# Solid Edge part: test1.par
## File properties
Author: CADCIM
Template: Normal.par
Last saved by: Cadcim
Revision: 2
Application: Solid Edge
Accuracy: 0.99
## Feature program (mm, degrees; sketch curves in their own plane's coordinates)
sketch for "unnamed Protrusion 1" #1 plane through (0, 0, 0) normal (0, 0, 1) x-axis (1, 0, 0)
  line (-47.52, 0) -> (-47.52, 46.944)
  line (-47.52, 46.944) -> (47.52, 46.944)
  line (47.52, 46.944) -> (47.52, 0)
  line (47.52, 0) -> (-47.52, 0)
sketch for "unnamed Protrusion 1" #2 plane through (0, 0, 0) normal (0, 0, 1) x-axis (1, 0, 0)
  circle centre (-33.4173, 33.1293) radius 7.1111
sketch for "unnamed Protrusion 1" #3 plane through (0, 0, 0) normal (0, 0, 1) x-axis (1, 0, 0)
  circle centre (0, 13.2015) radius 7.2161
sketch for "unnamed Protrusion 1" #4 plane through (0, 0, 0) normal (0, 0, 1) x-axis (1, 0, 0)
  circle centre (36.4831, 33.1293) radius 6.1622
extrude "unnamed Protrusion 1" add finite 6.35 along +normal
sketch for "ExtrudedProtrusion_2" #1 plane through (0, 23.472, 6.35) normal (0, 0, 1) x-axis (0, 1, 0)
sketch for "ExtrudedProtrusion_2" #2 plane through (0, 23.472, 6.35) normal (0, 0, 1) x-axis (0, 1, 0)
sketch for "ExtrudedProtrusion_2" #3 plane through (0, 23.472, 6.35) normal (0, 0, 1) x-axis (0, 1, 0)
  circle centre (-10.2705, 0) radius 7.2161
extrude "ExtrudedProtrusion_2" add finite 28.575 along -normal
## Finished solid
Body 1: solid body, 12 faces, 18 edges, 8 vertices.
  Faces by surface: plane 9, cylinder 3
  Edges by curve: line 12, circle 6
Bounding box of the edges (mm): 95.040 x 46.944 x 28.575, from (-47.52, 0, -22.225) to (47.52, 46.944, 6.35).
Cylindrical faces by radius (mm): R6.1622 x1, R7.1111 x1, R7.2161 x1
Planar faces by outward normal: +x 1, +y 1, +z 1, -x 1, -y 1, -z 4
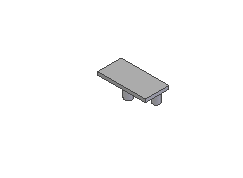
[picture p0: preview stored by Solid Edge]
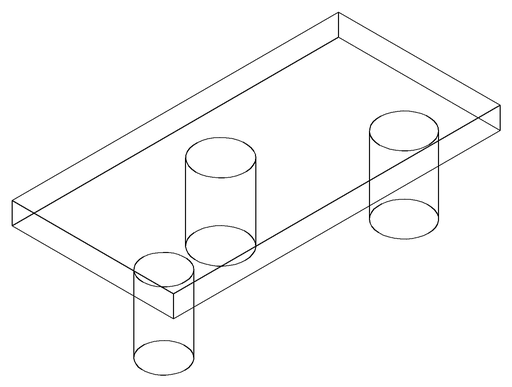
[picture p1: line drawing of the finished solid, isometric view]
